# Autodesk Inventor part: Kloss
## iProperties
Company: Autodesk EMEA
Shininess: 64.0
Length Units: 11269
Angle Units: 11279
Time Units: 11290
Mass Units: 11283
Length Display Precision: 3
Angle Display Precision: 2
Compacted: True
Part Number: Kloss
Document SubType Name: Modeling
Created: 2002-08
Designer: Franz Kaltseis
Density: 0.0
Volumn: 0.0
Area: 0.0
PropertySet Name: Model Information
Control State: 0
Master: False
Checked Out: False
Author: Franz Kaltseis
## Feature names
1. Extrusion1
